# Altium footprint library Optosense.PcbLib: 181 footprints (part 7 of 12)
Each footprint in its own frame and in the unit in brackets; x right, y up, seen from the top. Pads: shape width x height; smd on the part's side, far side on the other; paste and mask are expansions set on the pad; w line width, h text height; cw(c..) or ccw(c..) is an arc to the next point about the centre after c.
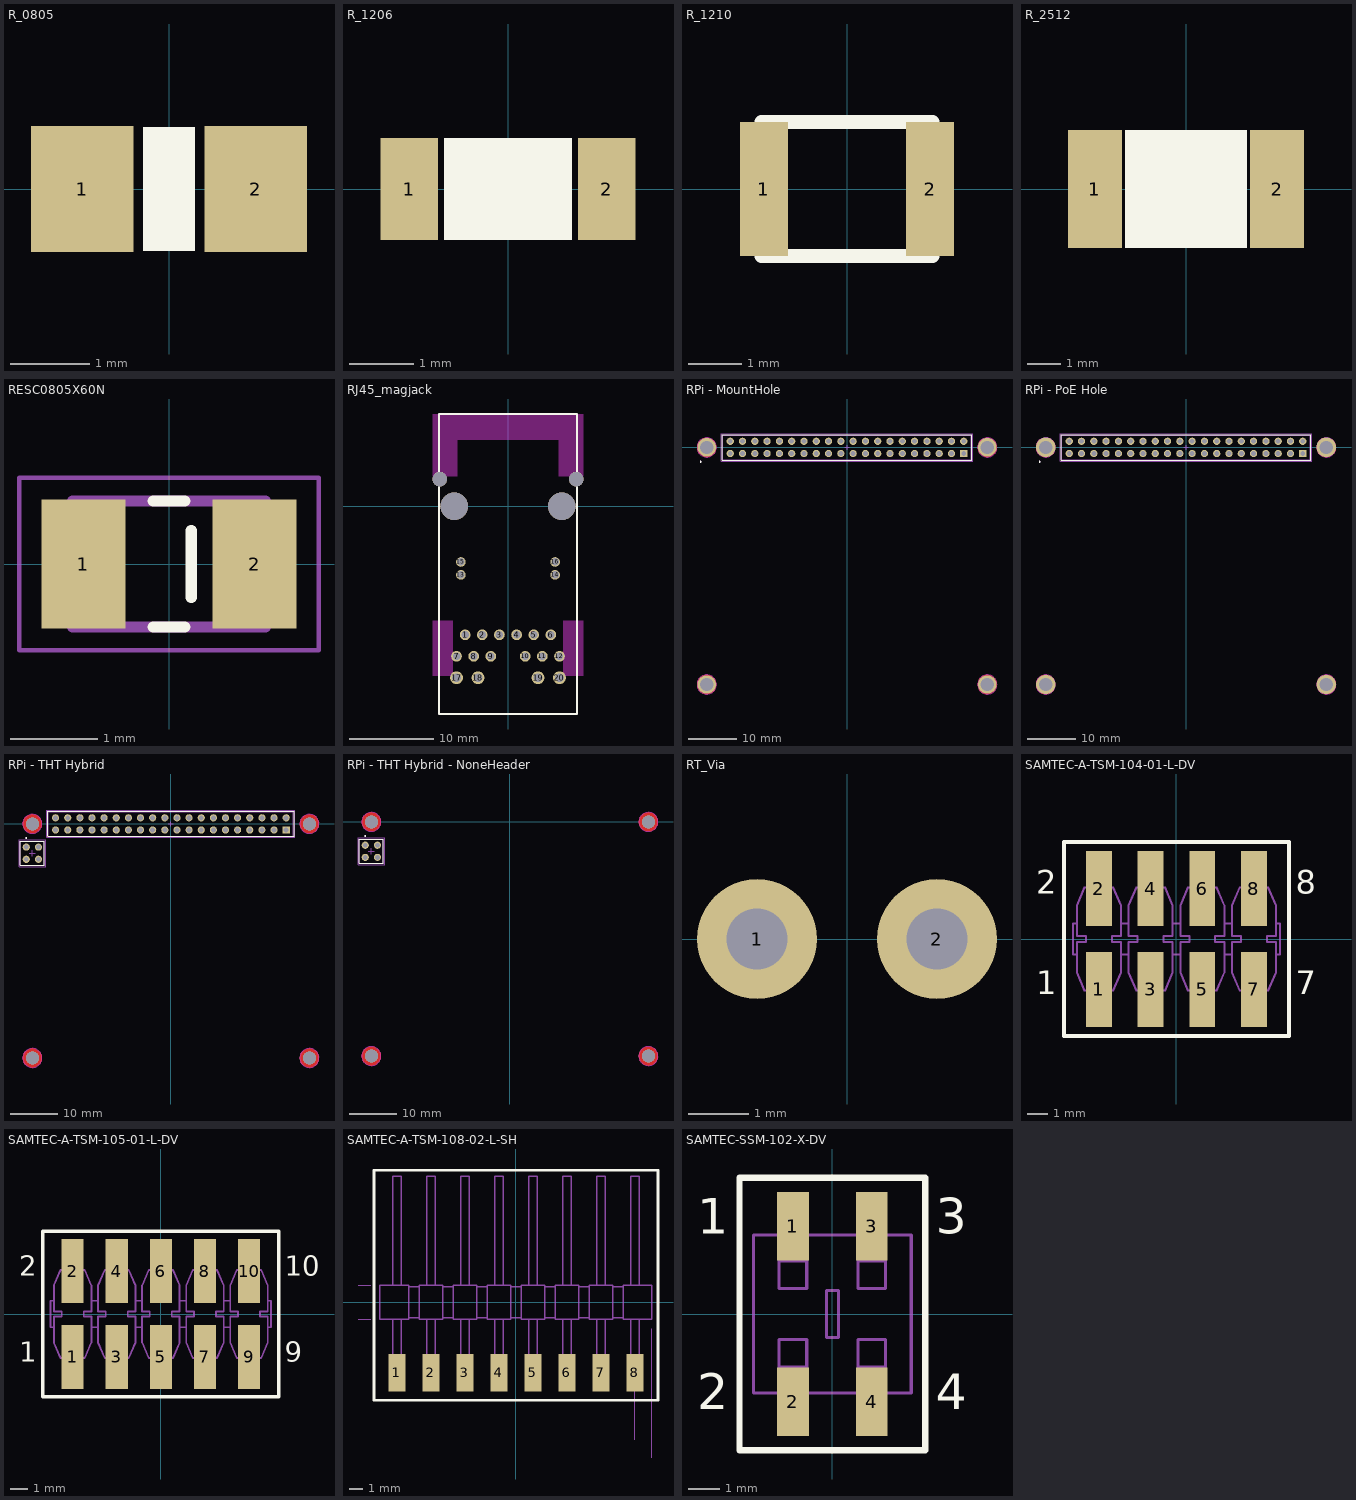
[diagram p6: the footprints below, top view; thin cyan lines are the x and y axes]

## R_0805 [mm]
pads (2):
  rect 1.3x1.6 smd: 1(-1.1,0) 2(1.1,0)
Top Overlay:
  rectangle: -0.33,-0.787 0.33,0.787
3D body "User Library-RESC2012X05N.step": height 0.45, standoff 0, extent -1,-0.625 1,0.625

## R_1206 [mm]
pads (2):
  rect 0.9x1.6 smd: 1(-1.55,0) 2(1.55,0)
Top Overlay:
  rectangle: -1,-0.8 1,0.8
3D body "CircuitWorks-RESISTOR 1206.step": height 0.58, standoff 0.02, extent -1.6,-0.83 1.6,0.83

## R_1210 [mm]
pads (2):
  rect 0.9x2.5 smd: 1(-1.55,0) 2(1.55,0)
Top Overlay:
  lines w0.254: -1.6,-1.25 -1.6,1.25 1.6,1.25 1.6,-1.25 -1.6,-1.25
3D body "User Library-CAPC3225X10.step": height 1, standoff 0, extent -1.6,-1.25 1.6,1.25

## R_2512 [mm]
pads (2):
  rect 1.6x3.5 smd: 1(-2.7,0) 2(2.7,0)
Top Overlay:
  rectangle: -1.803,-1.753 1.803,1.753
3D body "CircuitWorks-RESISTOR 2512.step": height 0.63, standoff 0.02, extent -3.175,-1.63 3.175,1.63

## RESC0805X60N [mm]
pads (2):
  rect 0.96x1.47 smd: 1(-0.978,0) 2(0.978,0)
Top Overlay:
  lines w0.127: -0.18,-0.72 0.18,-0.72 ; -0.18,0.72 0.18,0.72 ; 0.254,-0.381 0.254,0.381
Mechanical 13:
  lines w0.127: -1.1,-0.72 -1.1,0.72 1.1,0.72 1.1,-0.72 -1.1,-0.72
Mechanical 15:
  lines w0.05: -1.708,-0.983 -1.708,0.983 1.708,0.983 1.708,-0.983 -1.708,-0.983

## RJ45_magjack [mil] "0826-1X1T-HS-F"
height 536
pads (20):
  round 50 hole 35: 1(-200,-600) 2(-120,-600) 3(-40,-600) 4(40,-600) 5(120,-600) 6(200,-600) 7(-240,-700) 8(-160,-700) 9(-80,-700) 10(80,-700) 11(160,-700) 12(240,-700)
  round 45 hole 35: 13(-220,-320) 14(220,-320) 15(-220,-260) 16(220,-260)
  round 60 hole 40: 17(-240,-800) 18(-140,-800) 19(140,-800) 20(240,-800)
via 317.5,125 diameter 67.5 hole 67.5
via -317.5,125 diameter 67.5 hole 67.5
via 250,0 diameter 128 hole 128
via -250,0 diameter 128 hole 128
Top Overlay:
  lines w10: -321,-969 -321,430 321,430 321,-969 -321,-969
Keep-Out Layer:
  region: 258,-790 351,-790 351,-535 258,-535
  region: -351,-790 -258,-790 -258,-535 -351,-535
  region: -351,140 -236,140 -236,310 236,310 236,140 351,140 351,430 -351,430
3D body "0826-1X1T-HS-F--3DModel-STEP-56544.STEP": height 610.75, standoff -145, extent -375.5,-861.99 375.89,442.78

## RPi [mm] "Socket Header, Pitch 2.54 mm, SMT, Vertical, dual row, 40p"
height 7.45
3D body "Raspberry Pi 4 Model B.STEP": height 14.7, standoff -5.2, extent -56.629,-54.825 32.361,3.575

## RPi - MountHole [mm] "Socket Header, Pitch 2.54 mm, SMT, Vertical, dual row, 40p"
height 7.45
pads (40):
  rect 1.5x1.5 hole 1.02: 1(24.13,-1.27)
  round 1.5 hole 1.02: 2(24.13,1.27) 3(21.59,-1.27) 4(21.59,1.27) 5(19.05,-1.27) 7(16.51,-1.27) 8(16.51,1.27) 10(13.97,1.27) 11(11.43,-1.27) 12(11.43,1.27) 13(8.89,-1.27) 15(6.35,-1.27) 16(6.35,1.27) 17(3.81,-1.27) 18(3.81,1.27) 19(1.27,-1.27) 21(-1.27,-1.27) 22(-1.27,1.27) 23(-3.81,-1.27) 24(-3.81,1.27) 26(-6.35,1.27) 27(-8.89,-1.27) 28(-8.89,1.27) 29(-11.43,-1.27) 31(-13.97,-1.27) 32(-13.97,1.27) 33(-16.51,-1.27) 35(-19.05,-1.27) 36(-19.05,1.27) 37(-21.59,-1.27) 38(-21.59,1.27) 40(-24.13,1.27) GND(-24.13,-1.27) GND(-16.51,1.27) GND(-11.43,1.27) GND(-6.35,-1.27) GND(1.27,1.27) GND(8.89,1.27) GND(13.97,-1.27) GND(19.05,1.27)
via 29,0 diameter 3.8 hole 2.75
via -29,-49 diameter 3.8 hole 2.75
via 29,-49 diameter 3.8 hole 2.75
via -29,0 diameter 3.8 hole 2.75
Top Layer:
  pour cut-out: 29,-51 28.803,-51 28.417,-50.923 28.053,-50.772 27.725,-50.553 27.447,-50.275 27.228,-49.947 27.077,-49.583 27,-49.197 27,-49 27,-48.803 27.077,-48.417 27.228,-48.053 27.447,-47.725 27.725,-47.447 28.053,-47.228 28.417,-47.077 28.803,-47 29,-47 29.197,-47 29.583,-47.077 29.947,-47.228 30.275,-47.447 30.553,-47.725 30.772,-48.053 30.923,-48.417 31,-48.803 31,-49 31,-49.197 30.923,-49.583 30.772,-49.947 30.554,-50.275 30.275,-50.554 29.947,-50.772 29.583,-50.923 29.197,-51
  pour cut-out: -29,-51 -29.197,-51 -29.583,-50.923 -29.947,-50.772 -30.275,-50.553 -30.553,-50.275 -30.772,-49.947 -30.923,-49.583 -31,-49.197 -31,-49 -31,-48.803 -30.923,-48.417 -30.772,-48.053 -30.553,-47.725 -30.275,-47.447 -29.947,-47.228 -29.583,-47.077 -29.197,-47 -29,-47 -28.803,-47 -28.417,-47.077 -28.053,-47.228 -27.725,-47.447 -27.447,-47.725 -27.228,-48.053 -27.077,-48.417 -27,-48.803 -27,-49 -27,-49.197 -27.077,-49.583 -27.228,-49.947 -27.446,-50.275 -27.725,-50.554 -28.053,-50.772 -28.417,-50.923 -28.803,-51
  pour cut-out: -29,-2 -29.197,-2 -29.583,-1.923 -29.947,-1.772 -30.275,-1.553 -30.553,-1.275 -30.772,-0.947 -30.923,-0.583 -31,-0.197 -31,0 -31,0.197 -30.923,0.583 -30.772,0.947 -30.553,1.275 -30.275,1.553 -29.947,1.772 -29.583,1.923 -29.197,2 -29,2 -28.803,2 -28.417,1.923 -28.053,1.772 -27.725,1.553 -27.447,1.275 -27.228,0.947 -27.077,0.583 -27,0.197 -27,0 -27,-0.197 -27.077,-0.583 -27.228,-0.947 -27.446,-1.275 -27.725,-1.553 -28.053,-1.772 -28.417,-1.923 -28.803,-2
  pour cut-out: 29,-2 28.803,-2 28.417,-1.923 28.053,-1.772 27.725,-1.554 27.446,-1.275 27.228,-0.947 27.077,-0.583 27,-0.197 27,0 27,0.197 27.077,0.583 27.228,0.947 27.446,1.275 27.725,1.553 28.053,1.772 28.417,1.923 28.803,2 29,2 29.197,2 29.583,1.923 29.947,1.772 30.275,1.553 30.553,1.275 30.772,0.947 30.923,0.583 31,0.197 31,0 31,-0.197 30.923,-0.583 30.772,-0.947 30.553,-1.275 30.275,-1.554 29.947,-1.772 29.583,-1.923 29.197,-2
Bottom Layer:
  pour cut-out: 29,-51 28.803,-51 28.417,-50.923 28.053,-50.772 27.725,-50.554 27.446,-50.275 27.228,-49.947 27.077,-49.583 27,-49.197 27,-49 27,-48.803 27.077,-48.417 27.228,-48.053 27.446,-47.725 27.725,-47.447 28.053,-47.228 28.417,-47.077 28.803,-47 29,-47 29.197,-47 29.583,-47.077 29.947,-47.228 30.275,-47.446 30.553,-47.725 30.772,-48.053 30.923,-48.417 31,-48.803 31,-49 31,-49.197 30.923,-49.583 30.772,-49.947 30.553,-50.275 30.275,-50.554 29.947,-50.772 29.583,-50.923 29.197,-51
  pour cut-out: -29,-51 -29.197,-51 -29.583,-50.923 -29.947,-50.772 -30.275,-50.554 -30.553,-50.275 -30.772,-49.947 -30.923,-49.583 -31,-49.197 -31,-49 -31,-48.803 -30.923,-48.417 -30.772,-48.053 -30.554,-47.725 -30.275,-47.447 -29.947,-47.228 -29.583,-47.077 -29.197,-47 -29,-47 -28.803,-47 -28.417,-47.077 -28.053,-47.228 -27.725,-47.446 -27.446,-47.725 -27.228,-48.053 -27.077,-48.417 -27,-48.803 -27,-49 -27,-49.197 -27.077,-49.583 -27.228,-49.947 -27.446,-50.275 -27.725,-50.554 -28.053,-50.772 -28.417,-50.923 -28.803,-51
  pour cut-out: 29,-2 28.803,-2 28.417,-1.923 28.053,-1.772 27.725,-1.554 27.446,-1.275 27.228,-0.947 27.077,-0.583 27,-0.197 27,0 27,0.197 27.077,0.583 27.228,0.947 27.446,1.275 27.725,1.553 28.053,1.772 28.417,1.923 28.803,2 29,2 29.197,2 29.583,1.923 29.947,1.772 30.275,1.553 30.553,1.275 30.772,0.947 30.923,0.583 31,0.197 31,0 31,-0.197 30.923,-0.583 30.772,-0.947 30.553,-1.275 30.275,-1.554 29.947,-1.772 29.583,-1.923 29.197,-2
  pour cut-out: -29,-2 -29.197,-2 -29.583,-1.923 -29.947,-1.772 -30.275,-1.554 -30.554,-1.275 -30.772,-0.947 -30.923,-0.583 -31,-0.197 -31,0 -31,0.197 -30.923,0.583 -30.772,0.947 -30.553,1.275 -30.275,1.553 -29.947,1.772 -29.583,1.923 -29.197,2 -29,2 -28.803,2 -28.417,1.923 -28.053,1.772 -27.725,1.553 -27.446,1.275 -27.228,0.947 -27.077,0.583 -27,0.197 -27,0 -27,-0.197 -27.077,-0.583 -27.228,-0.947 -27.447,-1.275 -27.725,-1.554 -28.053,-1.772 -28.417,-1.923 -28.803,-2
Top Overlay:
  circle w0.2: c-30.27,-2.95 r0.1
  lines w0.2: -25.775,-2.615 25.775,-2.615 25.775,2.615 -25.775,2.615 -25.775,-2.615
Bottom Overlay:
  lines w0.2: -25.775,-2.615 25.775,-2.615 25.775,2.615 -25.775,2.615 -25.775,-2.615
Keep-Out Layer:
  circle w0.254: c29,0 r2
  circle w0.254: c-29,0 r2
  circle w0.254: c29,-49 r2
  circle w0.254: c-29,-49 r2
Mechanical 13:
  circle w0.2: c-30.27,-2.95 r0.1
  lines w0.1: -25.65,-2.54 -25.65,2.54 25.65,2.54 25.65,-2.54 -25.65,-2.54
Mechanical 15:
  lines w0.05: -0.5,0 0.5,0 ; 0,-0.5 0,0.5 ; -25.975,-2.815 25.975,-2.815 25.975,2.815 -25.975,2.815 -25.975,-2.815
3D body "960240-6202-AR.STEP": height 8.55, standoff -9.74, extent -25.4,-2.511 25.35,2.489

## RPi - PoE Hole [mm] "Socket Header, Pitch 2.54 mm, SMT, Vertical, dual row, 40p"
height 7.45
pads (40):
  rect 1.5x1.5 hole 1.02: 1(24.13,-1.27)
  round 1.5 hole 1.02: 2(24.13,1.27) 3(21.59,-1.27) 4(21.59,1.27) 5(19.05,-1.27) 7(16.51,-1.27) 8(16.51,1.27) 10(13.97,1.27) 11(11.43,-1.27) 12(11.43,1.27) 13(8.89,-1.27) 15(6.35,-1.27) 16(6.35,1.27) 17(3.81,-1.27) 18(3.81,1.27) 19(1.27,-1.27) 21(-1.27,-1.27) 22(-1.27,1.27) 23(-3.81,-1.27) 24(-3.81,1.27) 26(-6.35,1.27) 27(-8.89,-1.27) 28(-8.89,1.27) 29(-11.43,-1.27) 31(-13.97,-1.27) 32(-13.97,1.27) 33(-16.51,-1.27) 35(-19.05,-1.27) 36(-19.05,1.27) 37(-21.59,-1.27) 38(-21.59,1.27) 40(-24.13,1.27) GND(-24.13,-1.27) GND(-16.51,1.27) GND(-11.43,1.27) GND(-6.35,-1.27) GND(1.27,1.27) GND(8.89,1.27) GND(13.97,-1.27) GND(19.05,1.27)
via 29,0 diameter 4 hole 2.75
via -29,-49 diameter 4 hole 2.75
via 29,-49 diameter 4 hole 2.75
via -29,0 diameter 4 hole 2.75
Top Layer:
  pour cut-out: 29,-51 28.803,-51 28.417,-50.923 28.053,-50.772 27.725,-50.553 27.447,-50.275 27.228,-49.947 27.077,-49.583 27,-49.197 27,-49 27,-48.803 27.077,-48.417 27.228,-48.053 27.447,-47.725 27.725,-47.447 28.053,-47.228 28.417,-47.077 28.803,-47 29,-47 29.197,-47 29.583,-47.077 29.947,-47.228 30.275,-47.447 30.553,-47.725 30.772,-48.053 30.923,-48.417 31,-48.803 31,-49 31,-49.197 30.923,-49.583 30.772,-49.947 30.554,-50.275 30.275,-50.554 29.947,-50.772 29.583,-50.923 29.197,-51
  pour cut-out: 29,-2 28.803,-2 28.417,-1.923 28.053,-1.772 27.725,-1.554 27.446,-1.275 27.228,-0.947 27.077,-0.583 27,-0.197 27,0 27,0.197 27.077,0.583 27.228,0.947 27.446,1.275 27.725,1.553 28.053,1.772 28.417,1.923 28.803,2 29,2 29.197,2 29.583,1.923 29.947,1.772 30.275,1.553 30.553,1.275 30.772,0.947 30.923,0.583 31,0.197 31,0 31,-0.197 30.923,-0.583 30.772,-0.947 30.553,-1.275 30.275,-1.554 29.947,-1.772 29.583,-1.923 29.197,-2
  pour cut-out: -29,-51 -29.197,-51 -29.583,-50.923 -29.947,-50.772 -30.275,-50.553 -30.553,-50.275 -30.772,-49.947 -30.923,-49.583 -31,-49.197 -31,-49 -31,-48.803 -30.923,-48.417 -30.772,-48.053 -30.553,-47.725 -30.275,-47.447 -29.947,-47.228 -29.583,-47.077 -29.197,-47 -29,-47 -28.803,-47 -28.417,-47.077 -28.053,-47.228 -27.725,-47.447 -27.447,-47.725 -27.228,-48.053 -27.077,-48.417 -27,-48.803 -27,-49 -27,-49.197 -27.077,-49.583 -27.228,-49.947 -27.446,-50.275 -27.725,-50.554 -28.053,-50.772 -28.417,-50.923 -28.803,-51
  pour cut-out: -29,-2 -29.197,-2 -29.583,-1.923 -29.947,-1.772 -30.275,-1.553 -30.553,-1.275 -30.772,-0.947 -30.923,-0.583 -31,-0.197 -31,0 -31,0.197 -30.923,0.583 -30.772,0.947 -30.553,1.275 -30.275,1.553 -29.947,1.772 -29.583,1.923 -29.197,2 -29,2 -28.803,2 -28.417,1.923 -28.053,1.772 -27.725,1.553 -27.447,1.275 -27.228,0.947 -27.077,0.583 -27,0.197 -27,0 -27,-0.197 -27.077,-0.583 -27.228,-0.947 -27.446,-1.275 -27.725,-1.553 -28.053,-1.772 -28.417,-1.923 -28.803,-2
Bottom Layer:
  pour cut-out: 29,-51 28.803,-51 28.417,-50.923 28.053,-50.772 27.725,-50.554 27.446,-50.275 27.228,-49.947 27.077,-49.583 27,-49.197 27,-49 27,-48.803 27.077,-48.417 27.228,-48.053 27.446,-47.725 27.725,-47.447 28.053,-47.228 28.417,-47.077 28.803,-47 29,-47 29.197,-47 29.583,-47.077 29.947,-47.228 30.275,-47.446 30.553,-47.725 30.772,-48.053 30.923,-48.417 31,-48.803 31,-49 31,-49.197 30.923,-49.583 30.772,-49.947 30.553,-50.275 30.275,-50.554 29.947,-50.772 29.583,-50.923 29.197,-51
  pour cut-out: -29,-51 -29.197,-51 -29.583,-50.923 -29.947,-50.772 -30.275,-50.554 -30.553,-50.275 -30.772,-49.947 -30.923,-49.583 -31,-49.197 -31,-49 -31,-48.803 -30.923,-48.417 -30.772,-48.053 -30.554,-47.725 -30.275,-47.447 -29.947,-47.228 -29.583,-47.077 -29.197,-47 -29,-47 -28.803,-47 -28.417,-47.077 -28.053,-47.228 -27.725,-47.446 -27.446,-47.725 -27.228,-48.053 -27.077,-48.417 -27,-48.803 -27,-49 -27,-49.197 -27.077,-49.583 -27.228,-49.947 -27.446,-50.275 -27.725,-50.554 -28.053,-50.772 -28.417,-50.923 -28.803,-51
  pour cut-out: -29,-2 -29.197,-2 -29.583,-1.923 -29.947,-1.772 -30.275,-1.554 -30.554,-1.275 -30.772,-0.947 -30.923,-0.583 -31,-0.197 -31,0 -31,0.197 -30.923,0.583 -30.772,0.947 -30.553,1.275 -30.275,1.553 -29.947,1.772 -29.583,1.923 -29.197,2 -29,2 -28.803,2 -28.417,1.923 -28.053,1.772 -27.725,1.553 -27.446,1.275 -27.228,0.947 -27.077,0.583 -27,0.197 -27,0 -27,-0.197 -27.077,-0.583 -27.228,-0.947 -27.447,-1.275 -27.725,-1.554 -28.053,-1.772 -28.417,-1.923 -28.803,-2
  pour cut-out: 29,-2 28.803,-2 28.417,-1.923 28.053,-1.772 27.725,-1.554 27.446,-1.275 27.228,-0.947 27.077,-0.583 27,-0.197 27,0 27,0.197 27.077,0.583 27.228,0.947 27.446,1.275 27.725,1.553 28.053,1.772 28.417,1.923 28.803,2 29,2 29.197,2 29.583,1.923 29.947,1.772 30.275,1.553 30.553,1.275 30.772,0.947 30.923,0.583 31,0.197 31,0 31,-0.197 30.923,-0.583 30.772,-0.947 30.553,-1.275 30.275,-1.554 29.947,-1.772 29.583,-1.923 29.197,-2
Top Overlay:
  circle w0.2: c-30.27,-2.95 r0.1
  lines w0.2: -25.775,-2.615 25.775,-2.615 25.775,2.615 -25.775,2.615 -25.775,-2.615
Bottom Overlay:
  lines w0.2: -25.775,-2.615 25.775,-2.615 25.775,2.615 -25.775,2.615 -25.775,-2.615
Keep-Out Layer:
  circle w0.254: c29,0 r2
  circle w0.254: c-29,0 r2
  circle w0.254: c29,-49 r2
  circle w0.254: c-29,-49 r2
Mechanical 13:
  circle w0.2: c-30.27,-2.95 r0.1
  lines w0.1: -25.65,-2.54 -25.65,2.54 25.65,2.54 25.65,-2.54 -25.65,-2.54
Mechanical 15:
  lines w0.05: -0.5,0 0.5,0 ; 0,-0.5 0,0.5 ; -25.975,-2.815 25.975,-2.815 25.975,2.815 -25.975,2.815 -25.975,-2.815
3D body "960240-6202-AR.STEP": height 8.55, standoff -9.74, extent -25.4,-2.511 25.35,2.489

## RPi - THT Hybrid [mm] "Socket Header, Pitch 2.54 mm, SMT, Vertical, dual row, 40p"
height 7.45
pads (44):
  rect 1.5x1.5 hole 1.02: 1(24.13,-1.27)
  round 1.5 hole 1.02: 1_PoE(-30.27,-4.87) 2(24.13,1.27) 2_PoE(-27.73,-4.87) 3(21.59,-1.27) 3_PoE(-27.73,-7.41) 4(21.59,1.27) 4_PoE(-30.27,-7.41) 5(19.05,-1.27) 7(16.51,-1.27) 8(16.51,1.27) 10(13.97,1.27) 11(11.43,-1.27) 12(11.43,1.27) 13(8.89,-1.27) 15(6.35,-1.27) 16(6.35,1.27) 17(3.81,-1.27) 18(3.81,1.27) 19(1.27,-1.27) 21(-1.27,-1.27) 22(-1.27,1.27) 23(-3.81,-1.27) 24(-3.81,1.27) 26(-6.35,1.27) 27(-8.89,-1.27) 28(-8.89,1.27) 29(-11.43,-1.27) 31(-13.97,-1.27) 32(-13.97,1.27) 33(-16.51,-1.27) 35(-19.05,-1.27) 36(-19.05,1.27) 37(-21.59,-1.27) 38(-21.59,1.27) 40(-24.13,1.27) GND(-24.13,-1.27) GND(-16.51,1.27) GND(-11.43,1.27) GND(-6.35,-1.27) GND(1.27,1.27) GND(8.89,1.27) GND(13.97,-1.27) GND(19.05,1.27)
via -29,0 diameter 2.75 hole 2.75
via 29,0 diameter 2.75 hole 2.75
via 29,-49 diameter 2.75 hole 2.75
via -29,-49 diameter 2.75 hole 2.75
Top Layer:
  pour cut-out: -29,-51 -29.197,-51 -29.583,-50.923 -29.947,-50.772 -30.275,-50.553 -30.553,-50.275 -30.772,-49.947 -30.923,-49.583 -31,-49.197 -31,-49 -31,-48.803 -30.923,-48.417 -30.772,-48.053 -30.553,-47.725 -30.275,-47.446 -29.947,-47.228 -29.583,-47.077 -29.197,-47 -29,-47 -28.803,-47 -28.417,-47.077 -28.053,-47.228 -27.725,-47.446 -27.446,-47.725 -27.228,-48.053 -27.077,-48.417 -27,-48.803 -27,-49 -27,-49.197 -27.077,-49.583 -27.228,-49.947 -27.446,-50.275 -27.725,-50.553 -28.053,-50.772 -28.417,-50.923 -28.803,-51
  pour cut-out: 29,-51 28.803,-51 28.417,-50.923 28.053,-50.772 27.725,-50.553 27.447,-50.275 27.228,-49.947 27.077,-49.583 27,-49.197 27,-49 27,-48.803 27.077,-48.417 27.228,-48.053 27.447,-47.725 27.725,-47.446 28.053,-47.228 28.417,-47.077 28.803,-47 29,-47 29.197,-47 29.583,-47.077 29.947,-47.228 30.275,-47.446 30.554,-47.725 30.772,-48.053 30.923,-48.417 31,-48.803 31,-49 31,-49.197 30.923,-49.583 30.772,-49.947 30.554,-50.275 30.275,-50.553 29.947,-50.772 29.583,-50.923 29.197,-51
  pour cut-out: 29,-2 28.803,-2 28.417,-1.923 28.053,-1.772 27.725,-1.553 27.447,-1.275 27.228,-0.947 27.077,-0.583 27,-0.197 27,0 27,0.197 27.077,0.583 27.228,0.947 27.447,1.275 27.725,1.554 28.053,1.772 28.417,1.923 28.803,2 29,2 29.197,2 29.583,1.923 29.947,1.772 30.275,1.554 30.554,1.275 30.772,0.947 30.923,0.583 31,0.197 31,0 31,-0.197 30.923,-0.583 30.772,-0.947 30.554,-1.275 30.275,-1.553 29.947,-1.772 29.583,-1.923 29.197,-2
  pour cut-out: -29,-2 -29.197,-2 -29.583,-1.923 -29.947,-1.772 -30.275,-1.553 -30.553,-1.275 -30.772,-0.947 -30.923,-0.583 -31,-0.197 -31,0 -31,0.197 -30.923,0.583 -30.772,0.947 -30.553,1.275 -30.275,1.554 -29.947,1.772 -29.583,1.923 -29.197,2 -29,2 -28.803,2 -28.417,1.923 -28.053,1.772 -27.725,1.554 -27.446,1.275 -27.228,0.947 -27.077,0.583 -27,0.197 -27,0 -27,-0.197 -27.077,-0.583 -27.228,-0.947 -27.446,-1.275 -27.725,-1.553 -28.053,-1.772 -28.417,-1.923 -28.803,-2
Bottom Layer:
  pour cut-out: -29,-51 -29.197,-51 -29.583,-50.923 -29.947,-50.772 -30.275,-50.554 -30.553,-50.275 -30.772,-49.947 -30.923,-49.583 -31,-49.197 -31,-49 -31,-48.803 -30.923,-48.417 -30.772,-48.053 -30.554,-47.725 -30.275,-47.447 -29.947,-47.228 -29.583,-47.077 -29.197,-47 -29,-47 -28.803,-47 -28.417,-47.077 -28.053,-47.228 -27.725,-47.446 -27.446,-47.725 -27.228,-48.053 -27.077,-48.417 -27,-48.803 -27,-49 -27,-49.197 -27.077,-49.583 -27.228,-49.947 -27.446,-50.275 -27.725,-50.554 -28.053,-50.772 -28.417,-50.923 -28.803,-51
  pour cut-out: 29,-51 28.803,-51 28.417,-50.923 28.053,-50.772 27.725,-50.554 27.447,-50.275 27.228,-49.947 27.077,-49.583 27,-49.197 27,-49 27,-48.803 27.077,-48.417 27.228,-48.053 27.446,-47.725 27.725,-47.447 28.053,-47.228 28.417,-47.077 28.803,-47 29,-47 29.197,-47 29.583,-47.077 29.947,-47.228 30.275,-47.446 30.554,-47.725 30.772,-48.053 30.923,-48.417 31,-48.803 31,-49 31,-49.197 30.923,-49.583 30.772,-49.947 30.554,-50.275 30.275,-50.554 29.947,-50.772 29.583,-50.923 29.197,-51
  pour cut-out: 29,-2 28.803,-2 28.417,-1.923 28.053,-1.772 27.725,-1.554 27.447,-1.275 27.228,-0.947 27.077,-0.583 27,-0.197 27,0 27,0.197 27.077,0.583 27.228,0.947 27.446,1.275 27.725,1.553 28.053,1.772 28.417,1.923 28.803,2 29,2 29.197,2 29.583,1.923 29.947,1.772 30.275,1.554 30.554,1.275 30.772,0.947 30.923,0.583 31,0.197 31,0 31,-0.197 30.923,-0.583 30.772,-0.947 30.554,-1.275 30.275,-1.554 29.947,-1.772 29.583,-1.923 29.197,-2
  pour cut-out: -29,-2 -29.197,-2 -29.583,-1.923 -29.947,-1.772 -30.275,-1.554 -30.553,-1.275 -30.772,-0.947 -30.923,-0.583 -31,-0.197 -31,0 -31,0.197 -30.923,0.583 -30.772,0.947 -30.554,1.275 -30.275,1.553 -29.947,1.772 -29.583,1.923 -29.197,2 -29,2 -28.803,2 -28.417,1.923 -28.053,1.772 -27.725,1.554 -27.446,1.275 -27.228,0.947 -27.077,0.583 -27,0.197 -27,0 -27,-0.197 -27.077,-0.583 -27.228,-0.947 -27.446,-1.275 -27.725,-1.554 -28.053,-1.772 -28.417,-1.923 -28.803,-2
Top Overlay:
  circle w0.2: c-30.27,-2.95 r0.1
  lines w0.2: -31.54,-8.68 -26.46,-8.68 -26.46,-3.6 -31.54,-3.6 -31.54,-8.68 ; -25.775,-2.615 -25.775,2.615 25.775,2.615 25.775,-2.615 -25.775,-2.615
Bottom Overlay:
  lines w0.2: -25.775,-2.615 -25.775,2.615 25.775,2.615 25.775,-2.615 -25.775,-2.615
Keep-Out Layer:
  circle w0.254: c-29,-49 r2
  circle w0.254: c29,-49 r2
  circle w0.254: c29,0 r2
  circle w0.254: c-29,0 r2
Mechanical 13:
  circle w0.2: c-30.27,-2.95 r0.1
  lines w0.1: -31.54,-8.68 -31.54,-3.6 -26.46,-3.6 -26.46,-8.68 -31.54,-8.68 ; -25.65,-2.54 25.65,-2.54 25.65,2.54 -25.65,2.54 -25.65,-2.54
Mechanical 15:
  lines w0.05: -29.635,-6.14 -28.365,-6.14 ; -29,-6.775 -29,-5.505 ; -0.5,0 0.5,0 ; 0,-0.5 0,0.5 ; -31.79,-8.93 -31.79,-3.35 -26.21,-3.35 -26.21,-8.93 -31.79,-8.93 ; -25.975,-2.815 25.975,-2.815 25.975,2.815 -25.975,2.815 -25.975,-2.815
3D body "960240-6202-AR.STEP": height 8.55, standoff -9.74, extent -25.4,-2.551 25.35,2.449
3D body "esq-102-44-t-d.stp": height 18.51, standoff -4.73, extent -31.811,-8.672 -26.223,-3.592

## RPi - THT Hybrid - NoneHeader [mm] "Socket Header, Pitch 2.54 mm, SMT, Vertical, dual row, 40p"
height 7.45
pads (4):
  round 1.5 hole 1.02: 1_PoE(-30.27,-4.87) 2_PoE(-27.73,-4.87) 3_PoE(-27.73,-7.41) 4_PoE(-30.27,-7.41)
via -29,-49 diameter 2.75 hole 2.75
via 29,-49 diameter 2.75 hole 2.75
via 29,0 diameter 2.75 hole 2.75
via -29,0 diameter 2.75 hole 2.75
Top Layer:
  pour cut-out: -29,-51 -29.197,-51 -29.583,-50.923 -29.947,-50.772 -30.275,-50.554 -30.553,-50.275 -30.772,-49.947 -30.923,-49.583 -31,-49.197 -31,-49 -31,-48.803 -30.923,-48.417 -30.772,-48.053 -30.553,-47.725 -30.275,-47.447 -29.947,-47.228 -29.583,-47.077 -29.197,-47 -29,-47 -28.803,-47 -28.417,-47.077 -28.053,-47.228 -27.725,-47.446 -27.446,-47.725 -27.228,-48.053 -27.077,-48.417 -27,-48.803 -27,-49 -27,-49.197 -27.077,-49.583 -27.228,-49.947 -27.446,-50.275 -27.725,-50.554 -28.053,-50.772 -28.417,-50.923 -28.803,-51
  pour cut-out: 29,-51 28.803,-51 28.417,-50.923 28.053,-50.772 27.725,-50.553 27.447,-50.275 27.228,-49.947 27.077,-49.583 27,-49.197 27,-49 27,-48.803 27.077,-48.417 27.228,-48.053 27.447,-47.725 27.725,-47.447 28.053,-47.228 28.417,-47.077 28.803,-47 29,-47 29.197,-47 29.583,-47.077 29.947,-47.228 30.275,-47.447 30.553,-47.725 30.772,-48.053 30.923,-48.417 31,-48.803 31,-49 31,-49.197 30.923,-49.583 30.772,-49.947 30.554,-50.275 30.275,-50.554 29.947,-50.772 29.583,-50.923 29.197,-51
  pour cut-out: -29,-2 -29.197,-2 -29.583,-1.923 -29.947,-1.772 -30.275,-1.553 -30.553,-1.275 -30.772,-0.947 -30.923,-0.583 -31,-0.197 -31,0 -31,0.197 -30.923,0.583 -30.772,0.947 -30.553,1.275 -30.275,1.553 -29.947,1.772 -29.583,1.923 -29.197,2 -29,2 -28.803,2 -28.417,1.923 -28.053,1.772 -27.725,1.553 -27.447,1.275 -27.228,0.947 -27.077,0.583 -27,0.197 -27,0 -27,-0.197 -27.077,-0.583 -27.228,-0.947 -27.446,-1.275 -27.725,-1.553 -28.053,-1.772 -28.417,-1.923 -28.803,-2
  pour cut-out: 29,-2 28.803,-2 28.417,-1.923 28.053,-1.772 27.725,-1.553 27.447,-1.275 27.228,-0.947 27.077,-0.583 27,-0.197 27,0 27,0.197 27.077,0.583 27.228,0.947 27.447,1.275 27.725,1.553 28.053,1.772 28.417,1.923 28.803,2 29,2 29.197,2 29.583,1.923 29.947,1.772 30.275,1.553 30.553,1.275 30.772,0.947 30.923,0.583 31,0.197 31,0 31,-0.197 30.923,-0.583 30.772,-0.947 30.554,-1.275 30.275,-1.553 29.947,-1.772 29.583,-1.923 29.197,-2
Bottom Layer:
  pour cut-out: -29,-51 -29.197,-51 -29.583,-50.923 -29.947,-50.772 -30.275,-50.554 -30.554,-50.275 -30.772,-49.947 -30.923,-49.583 -31,-49.197 -31,-48.803 -30.923,-48.417 -30.772,-48.053 -30.554,-47.725 -30.275,-47.446 -29.947,-47.228 -29.583,-47.077 -29.197,-47 -29,-47 -28.803,-47 -28.417,-47.077 -28.053,-47.228 -27.725,-47.447 -27.447,-47.725 -27.228,-48.053 -27.077,-48.417 -27,-48.803 -27,-49 -27,-49.197 -27.077,-49.583 -27.228,-49.947 -27.446,-50.275 -27.725,-50.554 -28.053,-50.772 -28.417,-50.923 -28.803,-51
  pour cut-out: 29,-51 28.803,-51 28.417,-50.923 28.053,-50.772 27.725,-50.554 27.446,-50.275 27.228,-49.947 27.077,-49.583 27,-49.197 27,-49 27,-48.803 27.077,-48.417 27.228,-48.053 27.446,-47.725 27.725,-47.447 28.053,-47.228 28.417,-47.077 28.803,-47 29,-47 29.197,-47 29.583,-47.077 29.947,-47.228 30.275,-47.446 30.553,-47.725 30.772,-48.053 30.923,-48.417 31,-48.803 31,-49 31,-49.197 30.923,-49.583 30.772,-49.947 30.553,-50.275 30.275,-50.554 29.947,-50.772 29.583,-50.923 29.197,-51
  pour cut-out: 29,-2 28.803,-2 28.417,-1.923 28.053,-1.772 27.725,-1.553 27.447,-1.275 27.228,-0.947 27.077,-0.583 27,-0.197 27,0 27,0.197 27.077,0.583 27.228,0.947 27.447,1.275 27.725,1.553 28.053,1.772 28.417,1.923 28.803,2 29,2 29.197,2 29.583,1.923 29.947,1.772 30.275,1.553 30.553,1.275 30.772,0.947 30.923,0.583 31,0.197 31,0 31,-0.197 30.923,-0.583 30.772,-0.947 30.554,-1.275 30.275,-1.553 29.947,-1.772 29.583,-1.923 29.197,-2
  pour cut-out: -29,-2 -29.197,-2 -29.583,-1.923 -29.947,-1.772 -30.275,-1.553 -30.553,-1.275 -30.772,-0.947 -30.923,-0.583 -31,-0.197 -31,0 -31,0.197 -30.923,0.583 -30.772,0.947 -30.553,1.275 -30.275,1.553 -29.947,1.772 -29.583,1.923 -29.197,2 -29,2 -28.803,2 -28.417,1.923 -28.053,1.772 -27.725,1.553 -27.447,1.275 -27.228,0.947 -27.077,0.583 -27,0.197 -27,0 -27,-0.197 -27.077,-0.583 -27.228,-0.947 -27.446,-1.275 -27.725,-1.553 -28.053,-1.772 -28.417,-1.923 -28.803,-2
Top Overlay:
  circle w0.2: c-30.27,-2.95 r0.1
  lines w0.2: -31.54,-8.68 -31.54,-3.6 -26.46,-3.6 -26.46,-8.68 -31.54,-8.68
Keep-Out Layer:
  circle w0.254: c-29,-49 r2
  circle w0.254: c29,-49 r2
  circle w0.254: c29,0 r2
  circle w0.254: c-29,0 r2
Mechanical 13:
  circle w0.2: c-30.27,-2.95 r0.1
  lines w0.1: -31.54,-8.68 -26.46,-8.68 -26.46,-3.6 -31.54,-3.6 -31.54,-8.68
Mechanical 15:
  lines w0.05: -29.635,-6.14 -28.365,-6.14 ; -29,-6.775 -29,-5.505 ; -31.79,-8.93 -26.21,-8.93 -26.21,-3.35 -31.79,-3.35 -31.79,-8.93
3D body "esq-102-44-t-d.stp": height 18.51, standoff -4.73, extent -31.808,-8.695 -26.22,-3.615

## RT_Via [mm] "NTCALUG01A103F161L"
pads (2):
  round 2 hole 1.02: 1(-1.5,0) 2(1.5,0)

## SAMTEC-A-TSM-104-01-L-DV [mm]
pads (8):
  rect 1.27x3.68 smd: 1(-3.81,-2.476) 2(-3.81,2.476) 3(-1.27,-2.476) 4(-1.27,2.476) 5(1.27,-2.476) 6(1.27,2.476) 7(3.81,-2.476) 8(3.81,2.476)
Top Overlay:
  lines w0.2: -5.53,-4.768 5.53,-4.768 5.53,4.768 -5.53,4.768 -5.53,-4.768
  text "8" at 5.871,1.842 h1.97
  text "7" at 5.871,-3.112 h1.97
  text "2" at -6.9,1.842 h1.97
  text "1" at -6.9,-3.112 h1.97
Top Paste:
  rectangle: 3.175,0.636 4.445,4.316
  rectangle: 3.175,-4.316 4.445,-0.636
  rectangle: 0.635,0.636 1.905,4.316
  rectangle: 0.635,-4.316 1.905,-0.636
  rectangle: -1.905,0.636 -0.635,4.316
  rectangle: -1.905,-4.316 -0.635,-0.636
  rectangle: -4.445,0.636 -3.175,4.316
  rectangle: -4.445,-4.316 -3.175,-0.636
Top Solder:
  rectangle: 3.124,0.585 4.496,4.367
  rectangle: 3.124,-4.367 4.496,-0.585
  rectangle: 0.584,0.585 1.956,4.367
  rectangle: 0.584,-4.367 1.956,-0.585
  rectangle: -1.956,0.585 -0.584,4.367
  rectangle: -1.956,-4.367 -0.584,-0.585
  rectangle: -4.496,0.585 -3.124,4.367
  rectangle: -4.496,-4.367 -3.124,-0.585
Mechanical 16:
  lines w0.1: -4.89,-0.762 -5.08,-0.762 -5.08,0.762 -4.89,0.762 ; -4.128,-2.54 -4.128,-3.721 -3.492,-3.721 -3.492,-2.54 ; -4.128,2.54 -4.128,3.721 -3.492,3.721 -3.492,2.54 ; -2.35,-0.762 -2.54,-0.762 -2.73,-0.762 ; -2.35,0.762 -2.54,0.762 -2.73,0.762 ; -1.588,-2.54 -1.588,-3.721 -0.952,-3.721 -0.952,-2.54 ; -1.588,2.54 -1.588,3.721 -0.952,3.721 -0.952,2.54 ; 0.19,-0.762 0,-0.762 -0.19,-0.762 ; 0.19,0.762 0,0.762 -0.19,0.762 ; 0.952,-2.54 0.952,-3.721 1.588,-3.721 1.588,-2.54 ; 0.952,2.54 0.952,3.721 1.588,3.721 1.588,2.54 ; 2.73,-0.762 2.54,-0.762 2.35,-0.762 ; 2.73,0.762 2.54,0.762 2.35,0.762 ; 3.492,-2.54 3.492,-3.721 4.128,-3.721 4.128,-2.54 ; 3.492,2.54 3.492,3.721 4.128,3.721 4.128,2.54 ; -2.73,-0.762 -2.73,-1.651 -3.112,-2.54 -4.508,-2.54 -4.89,-1.651 -4.89,-0.146 -4.445,-0.146 -4.445,0.146 -4.89,0.146 -4.89,1.651 -4.508,2.54 -3.112,2.54 -2.73,1.651 -2.73,0.762 ; -2.73,-0.762 -2.73,-0.146 -3.175,-0.146 -3.175,0.146 -2.73,0.146 -2.73,0.762 ; -0.19,-0.762 -0.19,-0.146 -0.635,-0.146 -0.635,0.146 -0.19,0.146 -0.19,0.762 ; -0.19,-0.762 -0.19,-1.651 -0.572,-2.54 -1.968,-2.54 -2.35,-1.651 -2.35,-0.146 -1.905,-0.146 -1.905,0.146 -2.35,0.146 -2.35,1.651 -1.968,2.54 -0.572,2.54 -0.19,1.651 -0.19,0.762 ; 2.35,-0.762 2.35,-0.146 1.905,-0.146 1.905,0.146 2.35,0.146 2.35,0.762 ; 2.35,-0.762 2.35,-1.651 1.968,-2.54 0.572,-2.54 0.19,-1.651 0.19,-0.146 0.635,-0.146 0.635,0.146 0.19,0.146 0.19,1.651 0.572,2.54 1.968,2.54 2.35,1.651 2.35,0.762 ; 4.89,-0.762 4.89,-0.146 4.445,-0.146 4.445,0.146 4.89,0.146 4.89,0.762 ; 4.89,-0.762 5.08,-0.762 5.08,0.762 4.89,0.762 ; 4.89,-0.762 4.89,-1.651 4.508,-2.54 3.112,-2.54 2.73,-1.651 2.73,-0.146 3.175,-0.146 3.175,0.146 2.73,0.146 2.73,1.651 3.112,2.54 4.508,2.54 4.89,1.651 4.89,0.762 ; -4.128,-1.588 -4.128,-0.952 -3.492,-0.952 -3.492,-1.588 -4.128,-1.588 ; -4.128,0.952 -4.128,1.588 -3.492,1.588 -3.492,0.952 -4.128,0.952 ; -1.588,-1.588 -0.952,-1.588 -0.952,-0.952 -1.588,-0.952 -1.588,-1.588 ; -1.588,0.952 -0.952,0.952 -0.952,1.588 -1.588,1.588 -1.588,0.952 ; 0.952,-1.588 1.588,-1.588 1.588,-0.952 0.952,-0.952 0.952,-1.588 ; 0.952,0.952 1.588,0.952 1.588,1.588 0.952,1.588 0.952,0.952 ; 3.492,-1.588 4.128,-1.588 4.128,-0.952 3.492,-0.952 3.492,-1.588 ; 3.492,0.952 4.128,0.952 4.128,1.588 3.492,1.588 3.492,0.952
  text "8" at 5.871,1.842 h1.97
  text "7" at 5.871,-3.112 h1.97
  text "2" at -6.9,1.842 h1.97
  text "1" at -6.9,-3.112 h1.97
Mechanical 42:
  lines w0.1: -5.53,-4.768 5.53,-4.768 5.53,4.768 -5.53,4.768 -5.53,-4.768
3D body "TSM-104-01-L-DV.stp": height 9.61, standoff -0.04, extent -5.08,-3.848 5.08,3.848

## SAMTEC-A-TSM-105-01-L-DV [mm]
pads (10):
  rect 1.27x3.68 smd: 1(-5.08,-2.476) 2(-5.08,2.476) 3(-2.54,-2.476) 4(-2.54,2.476) 5(0,-2.476) 6(0,2.476) 7(2.54,-2.476) 8(2.54,2.476) 9(5.08,-2.476) 10(5.08,2.476)
Top Overlay:
  lines w0.2: -6.8,-4.768 6.8,-4.768 6.8,4.768 -6.8,4.768 -6.8,-4.768
  text "10" at 7.141,1.842 h1.97
  text "9" at 7.141,-3.112 h1.97
  text "2" at -8.17,1.842 h1.97
  text "1" at -8.17,-3.112 h1.97
Top Paste:
  rectangle: 4.445,0.636 5.715,4.316
  rectangle: 4.445,-4.316 5.715,-0.636
  rectangle: 1.905,0.636 3.175,4.316
  rectangle: 1.905,-4.316 3.175,-0.636
  rectangle: -0.635,0.636 0.635,4.316
  rectangle: -0.635,-4.316 0.635,-0.636
  rectangle: -3.175,0.636 -1.905,4.316
  rectangle: -3.175,-4.316 -1.905,-0.636
  rectangle: -5.715,0.636 -4.445,4.316
  rectangle: -5.715,-4.316 -4.445,-0.636
Top Solder:
  rectangle: 4.394,0.585 5.766,4.367
  rectangle: 4.394,-4.367 5.766,-0.585
  rectangle: 1.854,0.585 3.226,4.367
  rectangle: 1.854,-4.367 3.226,-0.585
  rectangle: -0.686,0.585 0.686,4.367
  rectangle: -0.686,-4.367 0.686,-0.585
  rectangle: -3.226,0.585 -1.854,4.367
  rectangle: -3.226,-4.367 -1.854,-0.585
  rectangle: -5.766,0.585 -4.394,4.367
  rectangle: -5.766,-4.367 -4.394,-0.585
Mechanical 16:
  drawing of 182 lines, arcs and shapes, not listed
  text "10" at 7.141,1.842 h1.97
  text "9" at 7.141,-3.112 h1.97
  text "2" at -8.17,1.842 h1.97
  text "1" at -8.17,-3.112 h1.97
Mechanical 42:
  lines w0.1: -6.8,-4.768 6.8,-4.768 6.8,4.768 -6.8,4.768 -6.8,-4.768
3D body "TSM-105-01-L-DV-TR.stp": height 9.61, standoff -0.04, extent -6.35,-3.848 6.35,3.848

## SAMTEC-A-TSM-108-02-L-SH [mm]
pads (8):
  rect 1.27x2.8 smd: 1(-8.89,-5.283) 2(-6.35,-5.283) 3(-3.81,-5.283) 4(-1.27,-5.283) 5(1.27,-5.283) 6(3.81,-5.283) 7(6.35,-5.283) 8(8.89,-5.283)
Top Overlay:
  lines w0.2: -10.61,-7.324 10.61,-7.324 10.61,9.848 -10.61,9.848 -10.61,-7.324
Top Paste:
  rectangle: 8.255,-6.673 9.525,-3.873
  rectangle: 5.715,-6.673 6.985,-3.873
  rectangle: 3.175,-6.673 4.445,-3.873
  rectangle: 0.635,-6.673 1.905,-3.873
  rectangle: -1.905,-6.673 -0.635,-3.873
  rectangle: -4.445,-6.673 -3.175,-3.873
  rectangle: -6.985,-6.673 -5.715,-3.873
  rectangle: -9.525,-6.673 -8.255,-3.873
Top Solder:
  rectangle: 8.204,-6.724 9.576,-3.924
  rectangle: 5.664,-6.724 7.036,-3.924
  rectangle: 3.124,-6.724 4.496,-3.924
  rectangle: 0.584,-6.724 1.956,-3.924
  rectangle: -1.956,-6.724 -0.584,-3.924
  rectangle: -4.496,-6.724 -3.124,-3.924
  rectangle: -7.036,-6.724 -5.664,-3.924
  rectangle: -9.576,-6.724 -8.204,-3.924
Mechanical 16:
  lines w0.1: -9.208,-1.27 -9.208,-6.096 -8.572,-6.096 -8.572,-1.27 ; -9.208,1.27 -9.208,9.398 -8.572,9.398 -8.572,1.27 ; -8.001,-1.143 -7.62,-1.143 -7.239,-1.143 ; -8.001,1.143 -7.62,1.143 -7.239,1.143 ; -6.668,-1.27 -6.668,-6.096 -6.032,-6.096 -6.032,-1.27 ; -6.668,1.27 -6.668,9.398 -6.032,9.398 -6.032,1.27 ; -5.461,-1.143 -5.08,-1.143 -4.699,-1.143 ; -5.461,1.143 -5.08,1.143 -4.699,1.143 ; -4.128,-1.27 -4.128,-6.096 -3.492,-6.096 -3.492,-1.27 ; -4.128,1.27 -4.128,9.398 -3.492,9.398 -3.492,1.27 ; -2.921,-1.143 -2.54,-1.143 -2.159,-1.143 ; -2.921,1.143 -2.54,1.143 -2.159,1.143 ; -1.588,-1.27 -1.588,-6.096 -0.952,-6.096 -0.952,-1.27 ; -1.588,1.27 -1.588,9.398 -0.952,9.398 -0.952,1.27 ; -0.381,-1.143 0,-1.143 0.381,-1.143 ; -0.381,1.143 0,1.143 0.381,1.143 ; 0.952,-1.27 0.952,-6.096 1.588,-6.096 1.588,-1.27 ; 0.952,1.27 0.952,9.398 1.588,9.398 1.588,1.27 ; 2.159,-1.143 2.54,-1.143 2.921,-1.143 ; 2.159,1.143 2.54,1.143 2.921,1.143 ; 3.492,-1.27 3.492,-6.096 4.128,-6.096 4.128,-1.27 ; 3.492,1.27 3.492,9.398 4.128,9.398 4.128,1.27 ; 4.699,-1.143 5.08,-1.143 5.461,-1.143 ; 4.699,1.143 5.08,1.143 5.461,1.143 ; 6.032,-1.27 6.032,-6.096 6.668,-6.096 6.668,-1.27 ; 6.032,1.27 6.032,9.398 6.668,9.398 6.668,1.27 ; 7.239,-1.143 7.62,-1.143 8.001,-1.143 ; 7.239,1.143 7.62,1.143 8.001,1.143 ; 8.572,-1.27 8.572,-6.096 9.208,-6.096 9.208,-1.27 ; 8.572,1.27 8.572,9.398 9.208,9.398 9.208,1.27 ; -10.16,-1.27 -8.001,-1.27 -8.001,1.27 -10.16,1.27 -10.16,-1.27 ; -7.239,-1.27 -7.239,1.27 -5.461,1.27 -5.461,-1.27 -7.239,-1.27 ; -4.699,-1.27 -4.699,1.27 -2.921,1.27 -2.921,-1.27 -4.699,-1.27 ; -2.159,-1.27 -2.159,1.27 -0.381,1.27 -0.381,-1.27 -2.159,-1.27 ; 0.381,-1.27 0.381,1.27 2.159,1.27 2.159,-1.27 0.381,-1.27 ; 2.921,-1.27 2.921,1.27 4.699,1.27 4.699,-1.27 2.921,-1.27 ; 5.461,-1.27 5.461,1.27 7.239,1.27 7.239,-1.27 5.461,-1.27 ; 8.001,-1.27 8.001,1.27 10.16,1.27 10.16,-1.27 8.001,-1.27
Mechanical 40:
  lines w0: -11.801,-1.27 -10.861,-1.27 ; -11.801,1.27 -10.861,1.27 ; 8.89,-10.29 8.89,-5.984 ; 10.16,-11.61 10.16,-1.971
Mechanical 42:
  lines w0.1: -10.61,-7.324 10.61,-7.324 10.61,9.848 -10.61,9.848 -10.61,-7.324
3D body "TSM-108-02-L-SH-K.stp": height 3.17, standoff 0, extent -10.16,-6.35 10.16,9.144

## SAMTEC-SSM-102-X-DV [mm]
pads (4):
  rect 1.02x2.22 smd: 1(-1.27,2.826) 2(-1.27,-2.826) 3(1.27,2.826) 4(1.27,-2.826)
Top Overlay:
  lines w0.2: -2.99,-4.387 2.99,-4.387 2.99,4.387 -2.99,4.387 -2.99,-4.387
  text "3" at 3.331,2.191 h1.97
  text "4" at 3.331,-3.461 h1.97
  text "1" at -4.36,2.191 h1.97
  text "2" at -4.36,-3.461 h1.97
Top Paste:
  rectangle: 0.76,-3.936 1.78,-1.716
  rectangle: 0.76,1.716 1.78,3.936
  rectangle: -1.78,-3.936 -0.76,-1.716
  rectangle: -1.78,1.716 -0.76,3.936
Top Solder:
  rectangle: 0.709,-3.987 1.831,-1.665
  rectangle: 0.709,1.665 1.831,3.987
  rectangle: -1.831,-3.987 -0.709,-1.665
  rectangle: -1.831,1.665 -0.709,3.987
Mechanical 16:
  lines w0.1: -1.524,-2.54 -1.524,-3.518 -1.016,-3.518 -1.016,-2.54 ; -1.524,2.54 -1.524,3.518 -1.016,3.518 -1.016,2.54 ; 1.016,-2.54 1.016,-3.518 1.524,-3.518 1.524,-2.54 ; 1.016,2.54 1.016,3.518 1.524,3.518 1.524,2.54 ; -2.54,-2.54 0,-2.54 2.54,-2.54 2.54,2.54 0,2.54 -2.54,2.54 -2.54,-2.54 ; -1.714,-1.714 -1.714,-0.826 -0.826,-0.826 -0.826,-1.714 -1.714,-1.714 ; -1.714,0.826 -1.714,1.714 -0.826,1.714 -0.826,0.826 -1.714,0.826 ; -0.19,-0.762 0,-0.762 0.19,-0.762 0.19,0.762 0,0.762 -0.19,0.762 -0.19,-0.762 ; 0.826,-1.714 1.714,-1.714 1.714,-0.826 0.826,-0.826 0.826,-1.714 ; 0.826,0.826 1.714,0.826 1.714,1.714 0.826,1.714 0.826,0.826
  text "3" at 3.331,2.191 h1.97
  text "4" at 3.331,-3.461 h1.97
  text "1" at -4.36,2.191 h1.97
  text "2" at -4.36,-3.461 h1.97
3D body "SSM-102-S-DV.stp": height 7.32, standoff -0.1, extent -2.54,-3.518 2.54,3.518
